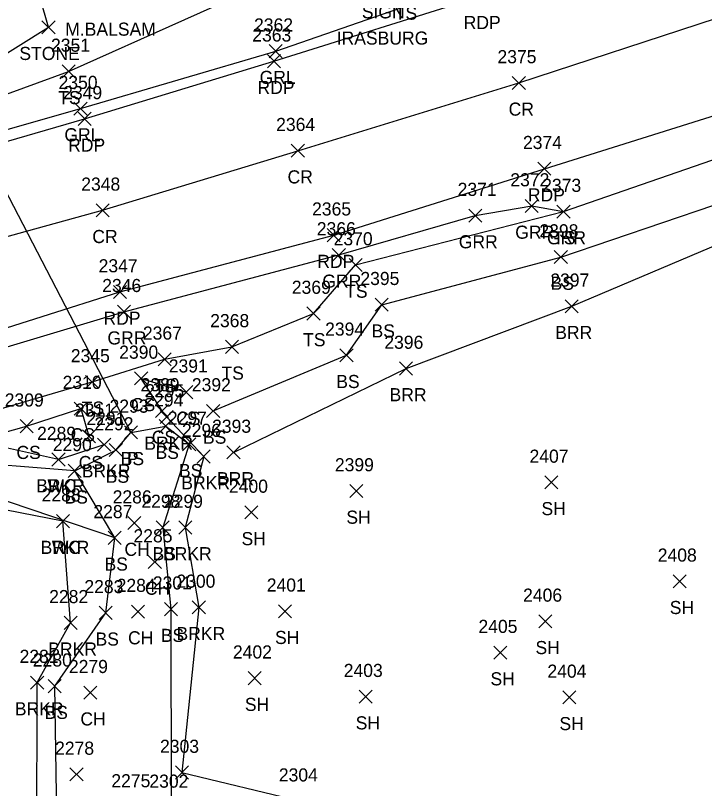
# Model space of a CAD drawing. Extents: x 1699408 to 1700423, y 840176 to 841410.
# Drawn here: x 1699920 to 1700025.1, y 840264.9 to 840382.8 of the extents above; entities that cross this region are included whole.
import ezdxf

# ---------------------------------------------------------------- set-up
doc = ezdxf.new("R2010")
doc.units = 0
for name, color, linetype in [('D_A', 7, 'Continuous'), ('D_I', 7, 'Continuous'), ('D_TIC', 7, 'Continuous'), ('DCP', 7, 'Continuous'), ('L_A', 7, 'Continuous'), ('L_C', 7, 'Continuous'), ('L_I', 7, 'Continuous'), ('L_TIC', 7, 'Continuous'), ('LABL', 7, 'Continuous'), ('LASF', 7, 'Continuous'), ('LAWE', 7, 'Continuous'), ('LELB', 7, 'Continuous'), ('P_A', 7, 'Continuous'), ('P_I', 7, 'Continuous'), ('P_TIC', 7, 'Continuous'), ('PET', 7, 'Continuous'), ('PRC', 7, 'Continuous'), ('R_A', 7, 'Continuous'), ('R_I', 7, 'Continuous'), ('R_TIC', 7, 'Continuous'), ('RGR', 7, 'Continuous'), ('S_A', 7, 'Continuous'), ('S_C', 7, 'Continuous')]:
    doc.layers.add(name, color=color, linetype=linetype)

msp = doc.modelspace()

# ---------------------------------------------------------------- linework, layer by layer
at = {"layer": 'D_TIC'}
for points in [[(1699936.64, 840318.19), (1699938.64, 840320.19)], [(1699938.64, 840318.19), (1699936.64, 840320.19)]]:
    msp.add_lwpolyline(points, dxfattribs=at)
at = {"layer": 'DCP'}
msp.add_lwpolyline([(1699906.1, 840379.9), (1699937.64, 840319.19)], dxfattribs=at)
at = {"layer": 'L_TIC'}
for points in [[(1699924.07, 840380), (1699926.07, 840382)], [(1699926.07, 840380), (1699924.07, 840382)], [(1699927.14, 840373.26), (1699929.14, 840375.26)], [(1699929.14, 840373.26), (1699927.14, 840375.26)], [(1700002.63, 840351.88), (1700004.63, 840353.88)], [(1700004.63, 840351.88), (1700002.63, 840353.88)], [(1700002.21, 840344.94), (1700004.21, 840346.94)], [(1700004.21, 840344.94), (1700002.21, 840346.94)], [(1699970.91, 840343.73), (1699972.91, 840345.73)], [(1699972.91, 840343.73), (1699970.91, 840345.73)], [(1699974.9, 840337.67), (1699976.9, 840339.67)], [(1699976.9, 840337.67), (1699974.9, 840339.67)], [(1700003.87, 840337.43), (1700005.87, 840339.43)], [(1700005.87, 840337.43), (1700003.87, 840339.43)], [(1699964.49, 840336.33), (1699966.49, 840338.33)], [(1699966.49, 840336.33), (1699964.49, 840338.33)], [(1699952.04, 840331.24), (1699954.04, 840333.24)], [(1699954.04, 840331.24), (1699952.04, 840333.24)], [(1699969.52, 840329.95), (1699971.52, 840331.95)], [(1699971.52, 840329.95), (1699969.52, 840331.95)], [(1699941.77, 840329.34), (1699943.77, 840331.34)], [(1699943.77, 840329.34), (1699941.77, 840331.34)], [(1699978.6, 840327.94), (1699980.6, 840329.94)], [(1699980.6, 840327.94), (1699978.6, 840329.94)], [(1699938.2, 840326.43), (1699940.2, 840328.43)], [(1699940.2, 840326.43), (1699938.2, 840328.43)], [(1699930.73, 840325.89), (1699932.73, 840327.89)], [(1699932.73, 840325.89), (1699930.73, 840327.89)], [(1699945.1, 840324.33), (1699947.1, 840326.33)], [(1699947.1, 840324.33), (1699945.1, 840326.33)], [(1699929, 840321.82), (1699931, 840323.82)], [(1699931, 840321.82), (1699929, 840323.82)], [(1699941.38, 840321.46), (1699943.38, 840323.46)], [(1699943.38, 840321.46), (1699941.38, 840323.46)], [(1699949.19, 840321.46), (1699951.19, 840323.46)], [(1699951.19, 840321.46), (1699949.19, 840323.46)], [(1699942.08, 840320.54), (1699944.08, 840322.54)], [(1699944.08, 840320.54), (1699942.08, 840322.54)], [(1699920.73, 840319.13), (1699922.73, 840321.13)], [(1699922.73, 840319.13), (1699920.73, 840321.13)], [(1699941.95, 840319.14), (1699943.95, 840321.14)], [(1699943.95, 840319.14), (1699941.95, 840321.14)], [(1699936.64, 840318.19), (1699938.64, 840320.19)], [(1699938.64, 840318.19), (1699936.64, 840320.19)], [(1699930.23, 840317.59), (1699932.23, 840319.59)], [(1699932.23, 840317.59), (1699930.23, 840319.59)], [(1699932.55, 840316.32), (1699934.55, 840318.32)], [(1699934.55, 840316.32), (1699932.55, 840318.32)], [(1699934.34, 840315.5), (1699936.34, 840317.5)], [(1699936.34, 840315.5), (1699934.34, 840317.5)], [(1699945.53, 840316.37), (1699947.53, 840318.37)], [(1699947.53, 840316.37), (1699945.53, 840318.37)], [(1699947.74, 840314.51), (1699949.74, 840316.51)], [(1699949.74, 840314.51), (1699947.74, 840316.51)], [(1699952.28, 840315.13), (1699954.28, 840317.13)], [(1699954.28, 840315.13), (1699952.28, 840317.13)], [(1699925.59, 840314.05), (1699927.59, 840316.05)], [(1699927.59, 840314.05), (1699925.59, 840316.05)], [(1699925.59, 840314.05), (1699927.59, 840316.05)], [(1699927.59, 840314.05), (1699925.59, 840316.05)], [(1699928.07, 840312.33), (1699930.07, 840314.33)], [(1699930.07, 840312.33), (1699928.07, 840314.33)], [(1699928.07, 840312.33), (1699930.07, 840314.33)], [(1699930.07, 840312.33), (1699928.07, 840314.33)], [(1700000.78, 840310.56), (1700002.78, 840312.56)], [(1700002.78, 840310.56), (1700000.78, 840312.56)], [(1699971.01, 840309.25), (1699973.01, 840311.25)], [(1699973.01, 840309.25), (1699971.01, 840311.25)], [(1699955.02, 840305.98), (1699957.02, 840307.98)], [(1699957.02, 840305.98), (1699955.02, 840307.98)], [(1699926.27, 840304.65), (1699928.27, 840306.65)], [(1699928.27, 840304.65), (1699926.27, 840306.65)], [(1699926.27, 840304.65), (1699928.27, 840306.65)], [(1699928.27, 840304.65), (1699926.27, 840306.65)], [(1699937.16, 840304.35), (1699939.16, 840306.35)], [(1699939.16, 840304.35), (1699937.16, 840306.35)], [(1699941.49, 840303.68), (1699943.49, 840305.68)], [(1699943.49, 840303.68), (1699941.49, 840305.68)], [(1699944.93, 840303.68), (1699946.93, 840305.68)], [(1699946.93, 840303.68), (1699944.93, 840305.68)], [(1699934.17, 840302.1), (1699936.17, 840304.1)], [(1699936.17, 840302.1), (1699934.17, 840304.1)], [(1699934.17, 840302.1), (1699936.17, 840304.1)], [(1699936.17, 840302.1), (1699934.17, 840304.1)], [(1699940.29, 840298.41), (1699942.29, 840300.41)], [(1699942.29, 840298.41), (1699940.29, 840300.41)], [(1700020.34, 840295.47), (1700022.34, 840297.47)], [(1700022.34, 840295.47), (1700020.34, 840297.47)], [(1699932.8, 840290.66), (1699934.8, 840292.66)], [(1699934.8, 840290.66), (1699932.8, 840292.66)], [(1699937.72, 840290.85), (1699939.72, 840292.85)], [(1699939.72, 840290.85), (1699937.72, 840292.85)], [(1699942.75, 840291.22), (1699944.75, 840293.22)], [(1699944.75, 840291.22), (1699942.75, 840293.22)], [(1699946.99, 840291.49), (1699948.99, 840293.49)], [(1699948.99, 840291.49), (1699946.99, 840293.49)], [(1699960.13, 840290.9), (1699962.13, 840292.9)], [(1699962.13, 840290.9), (1699960.13, 840292.9)], [(1699927.43, 840289.14), (1699929.43, 840291.14)], [(1699929.43, 840289.14), (1699927.43, 840291.14)], [(1699999.86, 840289.36), (1700001.86, 840291.36)], [(1700001.86, 840289.36), (1699999.86, 840291.36)], [(1699992.99, 840284.59), (1699994.99, 840286.59)], [(1699994.99, 840284.59), (1699992.99, 840286.59)], [(1699955.53, 840280.69), (1699957.53, 840282.69)], [(1699957.53, 840280.69), (1699955.53, 840282.69)], [(1699922.34, 840280.02), (1699924.34, 840282.02)], [(1699924.34, 840280.02), (1699922.34, 840282.02)], [(1699925.02, 840279.47), (1699927.02, 840281.47)], [(1699927.02, 840279.47), (1699925.02, 840281.47)], [(1699930.44, 840278.47), (1699932.44, 840280.47)], [(1699932.44, 840278.47), (1699930.44, 840280.47)], [(1699972.44, 840277.87), (1699974.44, 840279.87)], [(1699974.44, 840277.87), (1699972.44, 840279.87)], [(1700003.51, 840277.76), (1700005.51, 840279.76)], [(1700005.51, 840277.76), (1700003.51, 840279.76)], [(1699928.33, 840266.01), (1699930.33, 840268.01)], [(1699930.33, 840266.01), (1699928.33, 840268.01)], [(1699944.42, 840266.3), (1699946.42, 840268.3)], [(1699946.42, 840266.3), (1699944.42, 840268.3)]]:
    msp.add_lwpolyline(points, dxfattribs=at)
at = {"layer": 'LABL'}
msp.add_lwpolyline([(1699953.28, 840316.13), (1699979.6, 840328.94), (1700004.87, 840338.43), (1700035.26, 840351.3), (1700070.58, 840356.27), (1700115.47, 840370.34)], dxfattribs=at)
at = {"layer": 'LASF'}
msp.add_lwpolyline([(1699851.14, 840356.43), (1699867.77, 840361.02), (1699888.01, 840366.67), (1699907.74, 840370.19), (1699925.07, 840381), (1699922.64, 840389.58)], dxfattribs=at)
at = {"layer": 'LAWE'}
for points in [[(1699943.08, 840321.54), (1699948.74, 840315.51), (1699945.93, 840304.68), (1699947.99, 840292.49), (1699945.42, 840267.3), (1699963.54, 840262.93), (1699987.09, 840257.62)], [(1699926.59, 840315.05), (1699913.74, 840317.91), (1699894.91, 840318.62), (1699865.17, 840310.79)], [(1699926.59, 840315.05), (1699933.55, 840317.32)], [(1699927.27, 840305.65), (1699909.75, 840309.06), (1699896.15, 840307.95), (1699867.25, 840302.21)], [(1699988.05, 840237.95), (1699958.16, 840245.33), (1699923.29, 840256.74), (1699923.34, 840281.02), (1699928.43, 840290.14), (1699927.27, 840305.65)]]:
    msp.add_lwpolyline(points, dxfattribs=at)
at = {"layer": 'LELB'}
for points in [[(1699894.91, 840318.62), (1699909.54, 840320.37), (1699931.73, 840326.89), (1699942.77, 840330.34), (1699953.04, 840332.24), (1699965.49, 840337.33), (1699971.91, 840344.73), (1700003.63, 840352.88), (1700032.87, 840363), (1700063.25, 840372.76), (1700109.93, 840390.42), (1700140.91, 840399), (1700170.04, 840412.16), (1700222.58, 840432.8), (1700261.59, 840445.7), (1700307.68, 840461.11), (1700347.68, 840474.56), (1700384.18, 840486.92), (1700414.06, 840495.99)], [(1699950.19, 840322.46), (1699970.52, 840330.95), (1699975.9, 840338.67), (1700003.21, 840345.94), (1700034.35, 840356.49), (1700066.22, 840366.04), (1700111.96, 840382.71), (1700172.64, 840406.47), (1700188.14, 840417.18), (1700223.53, 840430.55), (1700261.76, 840444.29), (1700308.01, 840458.93), (1700347.92, 840472.31), (1700385.46, 840483.48), (1700416.04, 840491.19)], [(1699784.06, 840343.1), (1699812.78, 840343), (1699846.79, 840350.66), (1699873.28, 840357.14), (1699911.79, 840368.31), (1699928.14, 840374.26), (1699963.63, 840390.16), (1699976.97, 840400.87)], [(1699942.38, 840322.46), (1699939.2, 840327.43), (1699946.1, 840325.33)], [(1699913.74, 840317.91), (1699921.73, 840320.13), (1699930, 840322.82), (1699931.23, 840318.59)], [(1699990.76, 840239.56), (1699959.66, 840250.63), (1699926.41, 840257.45), (1699926.02, 840280.47), (1699933.8, 840291.66), (1699935.17, 840303.1), (1699929.07, 840313.33), (1699935.34, 840316.5), (1699937.64, 840319.19), (1699942.95, 840320.14), (1699946.53, 840317.37), (1699942.49, 840304.68), (1699943.75, 840292.22), (1699943.79, 840261.98), (1699961.11, 840259.71), (1699986.91, 840254.38)], [(1699929.07, 840313.33), (1699909.87, 840314.85), (1699896.6, 840315.58), (1699865.93, 840308.28), (1699866.62, 840305.3)], [(1699935.17, 840303.1), (1699909.47, 840311.82), (1699897.95, 840311.88), (1699866.62, 840305.3)]]:
    msp.add_lwpolyline(points, dxfattribs=at)
at = {"layer": 'P_TIC'}
for points in [[(1699958.45, 840374.82), (1699960.45, 840376.82)], [(1699960.45, 840374.82), (1699958.45, 840376.82)], [(1699995.81, 840371.51), (1699997.81, 840373.51)], [(1699997.81, 840371.51), (1699995.81, 840373.51)], [(1699929.57, 840366.02), (1699931.57, 840368.02)], [(1699931.57, 840366.02), (1699929.57, 840368.02)], [(1699962.1, 840361.17), (1699964.1, 840363.17)], [(1699964.1, 840361.17), (1699962.1, 840363.17)], [(1699999.7, 840358.42), (1700001.7, 840360.42)], [(1700001.7, 840358.42), (1699999.7, 840360.42)], [(1699932.32, 840352.07), (1699934.32, 840354.07)], [(1699934.32, 840352.07), (1699932.32, 840354.07)], [(1699967.58, 840348.28), (1699969.58, 840350.28)], [(1699969.58, 840348.28), (1699967.58, 840350.28)], [(1699934.97, 840339.61), (1699936.97, 840341.61)], [(1699936.97, 840339.61), (1699934.97, 840341.61)]]:
    msp.add_lwpolyline(points, dxfattribs=at)
at = {"layer": 'PET'}
for points in [[(1699430.72, 840228.22), (1699466.92, 840252.65), (1699493.58, 840268.87), (1699501.63, 840273.58), (1699505.33, 840277.49), (1699516.37, 840283.58), (1699542.26, 840294.23), (1699569.87, 840304.55), (1699598.29, 840312.45), (1699620.64, 840316.32), (1699670.9, 840322.33), (1699702.16, 840325.07), (1699741.15, 840329.16), (1699780.55, 840332.75), (1699814.05, 840338.23), (1699848.8, 840345.35), (1699873.3, 840351.35), (1699914.22, 840362.32), (1699930.57, 840367.02), (1699959.45, 840375.82), (1699990.91, 840385.72), (1700021.62, 840396.71), (1700043.81, 840403.93)], [(1699447.11, 840206.16), (1699475.63, 840224.65), (1699506.94, 840242.78), (1699536.09, 840256.08), (1699564.51, 840267.73), (1699591.88, 840277.12), (1699619.21, 840283.47), (1699647.22, 840288.99), (1699679.73, 840293.47), (1699710.33, 840296.95), (1699740.62, 840299.68), (1699772.35, 840302.79), (1699806.37, 840308.43), (1699836.08, 840313.39), (1699858.12, 840318.39), (1699877.08, 840323.18), (1699900.35, 840329.36), (1699935.97, 840340.61), (1699968.58, 840349.28), (1700000.7, 840359.42), (1700031.35, 840369.03)]]:
    msp.add_lwpolyline(points, dxfattribs=at)
at = {"layer": 'PRC'}
msp.add_lwpolyline([(1699438.11, 840217.33), (1699474.74, 840241.27), (1699500.34, 840255.97), (1699530.26, 840270.89), (1699558.33, 840282.59), (1699589.24, 840292.75), (1699616.86, 840299.45), (1699644.68, 840304.26), (1699678.81, 840308.53), (1699708.26, 840311.1), (1699739.11, 840314.27), (1699770.93, 840317.73), (1699804.23, 840322.43), (1699833.64, 840328), (1699873.5, 840337.02), (1699896.6, 840342.97), (1699933.32, 840353.07), (1699963.1, 840362.17), (1699996.81, 840372.51), (1700026.94, 840382.38)], dxfattribs=at)
at = {"layer": 'R_TIC'}
for points in [[(1699958.73, 840376.35), (1699960.73, 840378.35)], [(1699960.73, 840376.35), (1699958.73, 840378.35)], [(1699928.95, 840367.59), (1699930.95, 840369.59)], [(1699930.95, 840367.59), (1699928.95, 840369.59)], [(1699997.77, 840352.73), (1699999.77, 840354.73)], [(1699999.77, 840352.73), (1699997.77, 840354.73)], [(1699989.16, 840351.27), (1699991.16, 840353.27)], [(1699991.16, 840351.27), (1699989.16, 840353.27)], [(1700002.63, 840351.88), (1700004.63, 840353.88)], [(1700004.63, 840351.88), (1700002.63, 840353.88)], [(1699968.35, 840345.26), (1699970.35, 840347.26)], [(1699970.35, 840345.26), (1699968.35, 840347.26)], [(1699935.57, 840336.6), (1699937.57, 840338.6)], [(1699937.57, 840336.6), (1699935.57, 840338.6)]]:
    msp.add_lwpolyline(points, dxfattribs=at)
at = {"layer": 'RGR'}
for points in [[(1699728.48, 840335.43), (1699752.54, 840332.39), (1699780.34, 840334.41), (1699813.44, 840339.9), (1699849.41, 840347.4), (1699873.97, 840353.47), (1699916.95, 840364.91), (1699929.95, 840368.59), (1699959.73, 840377.35), (1699990.11, 840387.92), (1700008.42, 840397.8)], [(1699868.99, 840315.49), (1699900.9, 840326.88), (1699936.57, 840337.6), (1699969.35, 840346.26), (1699990.16, 840352.27), (1699998.77, 840353.73), (1700003.63, 840352.88)]]:
    msp.add_lwpolyline(points, dxfattribs=at)

# ---------------------------------------------------------------- texts
at = {"layer": 'D_A'}
msp.add_text('P', height=2, dxfattribs=at).set_placement((1699937.02, 840314.19))
at = {"layer": 'D_I'}
msp.add_text('2293', height=2, dxfattribs=at).set_placement((1699934.38, 840322.19))
at = {"layer": 'L_A'}
for s, p in [('TS', (1699977.88, 840382.15)), ('STONE', (1699920.62, 840376)), ('TS', (1699926.55, 840369.26)), ('TS', (1700002.04, 840347.88)), ('BS', (1700001.65, 840340.94)), ('TS', (1699970.32, 840339.73)), ('BS', (1699974.34, 840333.67)), ('BRR', (1700002.36, 840333.43)), ('TS', (1699963.9, 840332.33)), ('TS', (1699951.45, 840327.24)), ('TS', (1699941.18, 840325.34)), ('BS', (1699968.96, 840325.95)), ('BRR', (1699977.09, 840323.94)), ('TS', (1699930.14, 840321.89)), ('CS', (1699937.64, 840322.43)), ('CS', (1699944.55, 840320.33)), ('CS', (1699928.44, 840317.82)), ('CS', (1699940.82, 840317.46)), ('BS', (1699948.63, 840317.46)), ('BRKR', (1699939.68, 840316.54)), ('CS', (1699920.17, 840315.13)), ('BS', (1699941.39, 840315.14)), ('CS', (1699929.67, 840313.59)), ('BS', (1699936.08, 840314.19)), ('BRKR', (1699930.14, 840312.32)), ('BS', (1699944.97, 840312.37)), ('BS', (1699933.78, 840311.5)), ('BRR', (1699950.77, 840311.13)), ('BRKR', (1699923.18, 840310.05)), ('WC', (1699924.89, 840310.05)), ('BRKR', (1699945.33, 840310.51)), ('BS', (1699927.51, 840308.33)), ('BS', (1699927.51, 840308.33)), ('SH', (1700000.26, 840306.56)), ('SH', (1699970.5, 840305.25)), ('SH', (1699954.51, 840301.98)), ('BRKR', (1699923.86, 840300.65)), ('WC', (1699925.57, 840300.65)), ('CH', (1699936.65, 840300.35)), ('BS', (1699940.93, 840299.68)), ('BRKR', (1699942.53, 840299.68)), ('BS', (1699933.61, 840298.1)), ('BS', (1699933.61, 840298.1)), ('CH', (1699939.77, 840294.41)), ('SH', (1700019.83, 840291.47)), ('BS', (1699942.19, 840287.22)), ('BRKR', (1699944.59, 840287.49)), ('BS', (1699932.24, 840286.66)), ('CH', (1699937.2, 840286.85)), ('SH', (1699959.62, 840286.9)), ('BRKR', (1699925.02, 840285.14)), ('SH', (1699999.35, 840285.36)), ('SH', (1699992.48, 840280.59)), ('SH', (1699955.02, 840276.69)), ('BRKR', (1699919.93, 840276.02)), ('BS', (1699924.46, 840275.47)), ('CH', (1699929.93, 840274.47)), ('SH', (1699971.92, 840273.87)), ('SH', (1700003, 840273.76))]:
    msp.add_text(s, height=2, dxfattribs=at).set_placement(p)
at = {"layer": 'L_C'}
msp.add_text('M.BALSAM', height=2, dxfattribs=at).set_placement((1699927.62, 840379.71))
at = {"layer": 'L_I'}
for s, p in [('2351', (1699925.45, 840377.26)), ('2373', (1700000.37, 840355.88)), ('2398', (1699999.95, 840348.94)), ('2370', (1699968.56, 840347.73)), ('2395', (1699972.64, 840341.67)), ('2397', (1700001.61, 840341.43)), ('2369', (1699962.18, 840340.33)), ('2368', (1699949.73, 840335.24)), ('2367', (1699939.46, 840333.34)), ('2394', (1699967.26, 840333.95)), ('2396', (1699976.29, 840331.94)), ('2345', (1699928.47, 840329.89)), ('2390', (1699935.85, 840330.43)), ('2391', (1699943.41, 840328.33)), ('2310', (1699927.22, 840325.82)), ('2389', (1699939.11, 840325.46)), ('2392', (1699946.93, 840325.46)), ('2295', (1699939.82, 840324.54)), ('2309', (1699918.39, 840323.13)), ('2294', (1699939.69, 840323.14)), ('2311', (1699929.1, 840321.59)), ('2293', (1699934.38, 840322.19)), ('2291', (1699930.85, 840320.32)), ('2297', (1699943.27, 840320.37)), ('2292', (1699932.08, 840319.5)), ('2393', (1699950.02, 840319.13)), ('2289', (1699923.32, 840318.05)), ('2289', (1699923.32, 840318.05)), ('2296', (1699945.42, 840318.51)), ('2290', (1699925.72, 840316.33)), ('2290', (1699925.72, 840316.33)), ('2407', (1699998.44, 840314.56)), ('2399', (1699968.75, 840313.25)), ('2400', (1699952.59, 840309.98)), ('2288', (1699924.01, 840308.65)), ('2288', (1699924.01, 840308.65)), ('2286', (1699934.85, 840308.35)), ('2298', (1699939.23, 840307.68)), ('2299', (1699942.67, 840307.68)), ('2287', (1699931.91, 840306.1)), ('2287', (1699931.91, 840306.1)), ('2285', (1699938.03, 840302.41)), ('2408', (1700018, 840299.47)), ('2300', (1699944.57, 840295.49)), ('2283', (1699930.54, 840294.66)), ('2284', (1699935.46, 840294.85)), ('2301', (1699940.98, 840295.22)), ('2401', (1699958.36, 840294.9)), ('2282', (1699925.17, 840293.14)), ('2406', (1699997.46, 840293.36)), ('2405', (1699990.65, 840288.59)), ('2281', (1699920.65, 840284.02)), ('2402', (1699953.2, 840284.69)), ('2280', (1699922.68, 840283.47)), ('2279', (1699928.18, 840282.47)), ('2403', (1699970.1, 840281.87)), ('2404', (1700001.17, 840281.76)), ('2278', (1699926.07, 840270.01)), ('2303', (1699942.08, 840270.3)), ('2304', (1699960.2, 840265.93)), ('2275', (1699934.65, 840265.04)), ('2302', (1699940.45, 840264.98))]:
    msp.add_text(s, height=2, dxfattribs=at).set_placement(p)
at = {"layer": 'P_A'}
for s, p in [('RDP', (1699988.4, 840380.72)), ('RDP', (1699956.94, 840370.82)), ('CR', (1699995.25, 840367.51)), ('RDP', (1699928.06, 840362.02)), ('CR', (1699961.53, 840357.17)), ('RDP', (1699998.19, 840354.42)), ('CR', (1699931.75, 840348.07)), ('RDP', (1699966.07, 840344.28)), ('RDP', (1699933.45, 840335.61))]:
    msp.add_text(s, height=2, dxfattribs=at).set_placement(p)
at = {"layer": 'P_I'}
for s, p in [('2363', (1699956.15, 840378.82)), ('2375', (1699993.55, 840375.51)), ('2349', (1699927.3, 840370.02)), ('2364', (1699959.79, 840365.17)), ('2374', (1699997.44, 840362.42)), ('2348', (1699930.06, 840356.07)), ('2365', (1699965.27, 840352.28)), ('2347', (1699932.71, 840343.61))]:
    msp.add_text(s, height=2, dxfattribs=at).set_placement(p)
at = {"layer": 'R_A'}
for s, p in [('GRL', (1699957.27, 840372.35)), ('GRL', (1699927.49, 840363.59)), ('GRR', (1699996.26, 840348.73)), ('GRR', (1699987.65, 840347.27)), ('GRR', (1700001.11, 840347.88)), ('GRR', (1699966.84, 840341.26)), ('GRR', (1699934.06, 840332.6))]:
    msp.add_text(s, height=2, dxfattribs=at).set_placement(p)
at = {"layer": 'R_I'}
for s, p in [('2362', (1699956.42, 840380.35)), ('2350', (1699926.6, 840371.59)), ('2372', (1699995.51, 840356.73)), ('2373', (1700000.37, 840355.88)), ('2371', (1699987.47, 840355.27)), ('2366', (1699965.99, 840349.26)), ('2346', (1699933.26, 840340.6))]:
    msp.add_text(s, height=2, dxfattribs=at).set_placement(p)
at = {"layer": 'S_A'}
msp.add_text('SIGN', height=2, dxfattribs=at).set_placement((1699972.86, 840382.35))
at = {"layer": 'S_C'}
msp.add_text('IRASBURG', height=2, dxfattribs=at).set_placement((1699969.03, 840378.35))

doc.saveas('drawing.dxf')
